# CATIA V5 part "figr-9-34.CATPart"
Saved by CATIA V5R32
Part number: Part1
Bounding box of the stored display mesh (mm): x -250 to 0, y -60 to 60, z 0 to 100
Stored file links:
  D:\PROJECTS\Project 2022\CATIA V5 6R 2022\Resources\Part Files\c09_catia_v5_6r2022_prt\c09_catia_v5_6r2022_prt\figr-9-34.CATPart
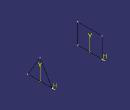
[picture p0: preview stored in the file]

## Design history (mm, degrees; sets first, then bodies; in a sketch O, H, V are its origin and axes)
Body1 (main body)
  Sketch1 on yz-plane, origin (0, 0, 0), H (0, 1, 0), V (0, 0, 1)
    point P1 (-60, 0)
    line L1 (-60, 0) -> (0, 100)
    point P2 (0, 100)
    line L2 (0, 100) -> (60, 0)
    point P3 (60, 0)
    line L3 (60, 0) -> (-60, 0)
    coincidence: P1 H, P2 V, P3 H
    horizontal: L3 H
    midpoint: O L3
  Sketch2, origin (-250, 0, 0), H (0, 1, 0), V (0, 0, 1)
    point P1 (-60, 0)
    line L1 (-60, 0) -> (60, 0)
    line L2 (60, 0) -> (60, 100)
    line L3 (60, 100) -> (-60, 100)
    line L4 (-60, 100) -> (-60, 0)
    coincidence: P1 H
    horizontal: L1 H, L3 H
    vertical: L2 V, L4 V
  Loft1: Sections (Sketch1; Sketch2), SectionCouplingPoints ({coupling CouplingPoints (vertex [element of Sketch1 | element of Sketch1]; vertex [element of Sketch2 | element of Sketch2])}; {coupling CouplingPoints (vertex [element of Sketch1 | element of Sketch1]; vertex [element of Sketch2 | element of Sketch2])}; {coupling CouplingPoints (vertex [element of Sketch1 | element of Sketch1]; vertex [element of Sketch2 | element of Sketch2])})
